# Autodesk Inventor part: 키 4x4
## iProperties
Company: 한국ATC센터
Created: 2014-10
Part Number: 키 4x4
Document SubType Name: Modeling
Designer: KYOUNG IL JANG
Density: 1 g/cm^3
Mass: 0.210265 g
Surface Area: 2.35398 cm^2
Volume: 0.210265 cm^3
Author: KYOUNG IL JANG
Revision Number: 1
